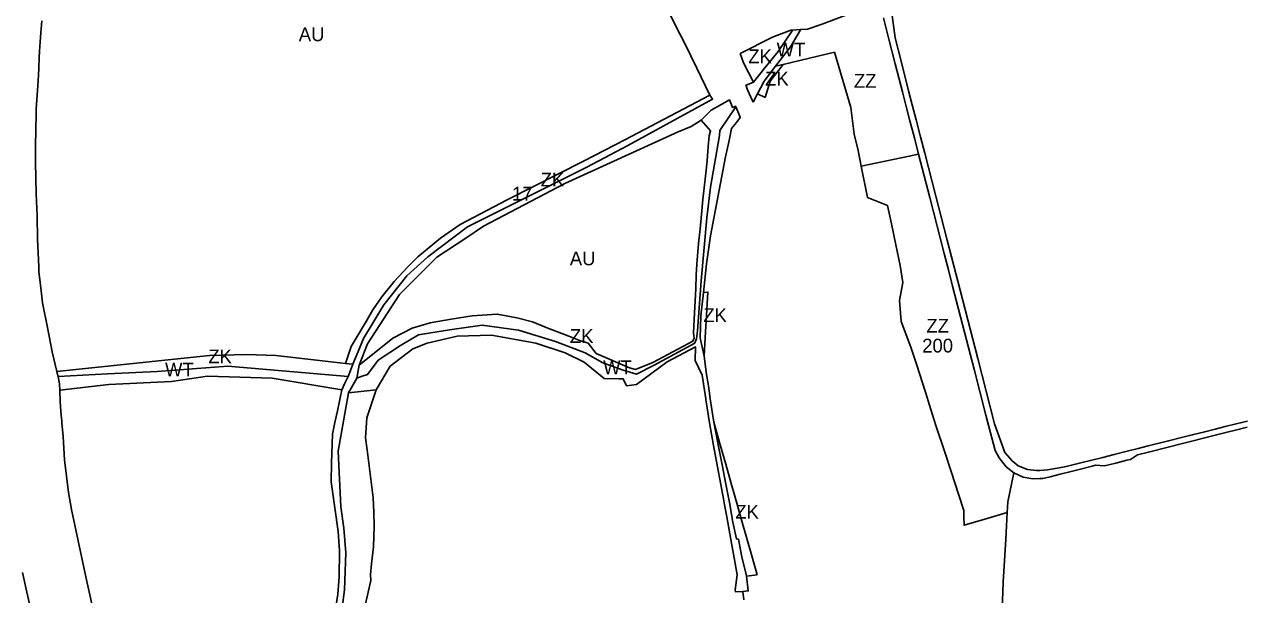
# Model space of a CAD drawing. Extents: x -521939 to -516426, y -1197857 to -1189551.
# Drawn here: x -520821 to -519936, y -1191056 to -1190643 of the extents above; entities that cross this region are included whole.
import ezdxf

# ---------------------------------------------------------------- set-up
doc = ezdxf.new("R2010")
doc.units = 0
for name, color, linetype in [('90640013', 7, 'Continuous'), ('90670013', 7, 'Continuous'), ('90670023', 7, 'Continuous'), ('90710013', 7, 'Continuous'), ('90710023', 7, 'Continuous'), ('90750013', 7, 'Continuous'), ('90760013', 7, 'Continuous'), ('ID_navrh', 7, 'Continuous')]:
    doc.layers.add(name, color=color, linetype=linetype)

msp = doc.modelspace()

# ---------------------------------------------------------------- linework, layer by layer
at = {"layer": '90640013'}
for points in [[(-520293.09, -1190699.05), (-520289.87, -1190692.86), (-520285.12, -1190683.72), (-520277.02, -1190672.92), (-520266.06, -1190658.73), (-520258.89, -1190646.59), (-520258.89, -1190646.14), (-520264.87, -1190646.73), (-520264.75, -1190647.22), (-520275.05, -1190662.18), (-520284.6, -1190674.13), (-520292.81, -1190684.4), (-520297.57, -1190686.32), (-520298.45, -1190686.69), (-520298.24, -1190687.15), (-520297.09, -1190690.03), (-520294.84, -1190695.28), (-520293.32, -1190698.51), (-520293.09, -1190699.05)], [(-520300.69, -1191053.74), (-520296.62, -1191053.24), (-520297.9, -1191042.46), (-520298.38, -1191040.48), (-520301.26, -1191028.49), (-520303.81, -1191015.76), (-520305.26, -1191015.58), (-520307.87, -1191003.34), (-520308.58, -1190999.2), (-520310.09, -1190990.35), (-520312.91, -1190975.8), (-520315.64, -1190961.74), (-520315.85, -1190960.65), (-520318.42, -1190947.44), (-520318.74, -1190945.79), (-520321.62, -1190930.94), (-520323.01, -1190921.74), (-520324.17, -1190914.08), (-520324.81, -1190909.83), (-520325.83, -1190903.07), (-520326.85, -1190896.32), (-520328.57, -1190882.98), (-520331.4, -1190869.77), (-520330.94, -1190853.79), (-520329.11, -1190836.87), (-520326.88, -1190816.15), (-520324.02, -1190795.87), (-520313.16, -1190738.47), (-520310.59, -1190726.63), (-520308.72, -1190718.11), (-520305.27, -1190713.64), (-520302.42, -1190709.94), (-520303.5, -1190707.28), (-520305.63, -1190702.37), (-520317.2, -1190719.56), (-520317.55, -1190723.04), (-520324.05, -1190760.6), (-520326.6, -1190782.85), (-520330.8, -1190828.36), (-520333.48, -1190864.82), (-520334.12, -1190870.43), (-520335.3, -1190873.36), (-520335.39, -1190873.58), (-520364.84, -1190889.55), (-520377.6, -1190896.01), (-520387.42, -1190893.21), (-520401.95, -1190887.98), (-520414.96, -1190880.71), (-520436.37, -1190872.55), (-520463.15, -1190864.14), (-520489.53, -1190860.7), (-520513.25, -1190864.01), (-520535.56, -1190867.71), (-520548.81, -1190875.36), (-520564.88, -1190886.07), (-520572.53, -1190896.27), (-520576.48, -1190897.66), (-520580.44, -1190899.06), (-520586.27, -1190909.59), (-520566.41, -1190907.41), (-520556.17, -1190890.3), (-520539.78, -1190877.79), (-520529.48, -1190873.72), (-520507.51, -1190868.51), (-520482.81, -1190867.75), (-520450.71, -1190873.64), (-520429.39, -1190880.67), (-520415.69, -1190887.37), (-520401.05, -1190899.23), (-520390.41, -1190899.46), (-520387.21, -1190899.53), (-520384.79, -1190904.6), (-520377.57, -1190903.54), (-520355.52, -1190887.16), (-520334.81, -1190876.42), (-520335.23, -1190886.32), (-520330.14, -1190896.79), (-520327.45, -1190914.09), (-520327.38, -1190914.52), (-520324.76, -1190931.38), (-520324.76, -1190931.39), (-520321.74, -1190947.87), (-520319.13, -1190962.12), (-520316.55, -1190976.2), (-520314.68, -1190986.43), (-520313.89, -1190990.74), (-520312.27, -1190999.57), (-520309.26, -1191016.03), (-520306.84, -1191029.26), (-520304.6, -1191041.48), (-520306.2, -1191052.37), (-520305.85, -1191054), (-520300.69, -1191053.74)], [(-520795.63, -1190907.7), (-520760.13, -1190903.61), (-520714.74, -1190901.46), (-520688.67, -1190897.65), (-520641.66, -1190899.02), (-520591.21, -1190907.38), (-520588.94, -1190902.65), (-520586.68, -1190897.92), (-520673.92, -1190890.22), (-520725.06, -1190894.18), (-520760.94, -1190895.97), (-520796.83, -1190897.77), (-520795.84, -1190903.04), (-520795.63, -1190907.7)]]:
    msp.add_lwpolyline(points, dxfattribs=at)
at = {"layer": '90670013'}
for points in [[(-520212.3, -1190630.74), (-520243.84, -1190642.67), (-520253.81, -1190645.91), (-520258.89, -1190646.14), (-520258.89, -1190646.59), (-520266.06, -1190658.73), (-520277.02, -1190672.92)], [(-520277.02, -1190672.92), (-520271.45, -1190671.59), (-520234.25, -1190662.74), (-520223.64, -1190698.57), (-520222.41, -1190702.71), (-520221.14, -1190712.4), (-520219.87, -1190722.1), (-520217, -1190733.95), (-520214.93, -1190745.28), (-520179.93, -1190738.09), (-520173.21, -1190736.7), (-520176.29, -1190724.77), (-520179.47, -1190712.51), (-520182.14, -1190702.16), (-520184.89, -1190691.51), (-520190.1, -1190671.19), (-520194.85, -1190653.37), (-520198.74, -1190637.77)], [(-519935.17, -1190934.6), (-519942.63, -1190936.51), (-519950.59, -1190938.53), (-519958.33, -1190940.45), (-519965.72, -1190942.29), (-519975.1, -1190944.67), (-519983.03, -1190946.64), (-519992.34, -1190949.01), (-520006.62, -1190952.57), (-520014.63, -1190954.57), (-520019.58, -1190957.88), (-520022.33, -1190958.55), (-520030.34, -1190960.58), (-520038.54, -1190962.66), (-520045.1, -1190962.2), (-520047.4, -1190962.76), (-520055.99, -1190964.97), (-520062.63, -1190966.61), (-520070.6, -1190968.71), (-520077.83, -1190970.45), (-520083.18, -1190971.78), (-520085.31, -1190971.83), (-520090.37, -1190971.94), (-520097.48, -1190970.69), (-520104.07, -1190967.71), (-520108.58, -1190988.66), (-520109.01, -1190996.4)], [(-520109.01, -1190996.4), (-520110.09, -1191015.65), (-520111.98, -1191046.9), (-520113.12, -1191080.75)]]:
    msp.add_lwpolyline(points, dxfattribs=at)
at = {"layer": '90670023'}
msp.add_lwpolyline([(-520109.01, -1190996.4), (-520108.58, -1190988.66), (-520104.07, -1190967.71), (-520109.65, -1190963.19), (-520114.88, -1190956.87), (-520117.77, -1190951.37), (-520124.37, -1190925.82), (-520132.72, -1190893.53), (-520148.53, -1190832.37), (-520151.61, -1190820.43), (-520154.72, -1190808.75), (-520165.15, -1190767.99), (-520173.21, -1190736.7), (-520179.93, -1190738.09), (-520214.93, -1190745.28), (-520210.17, -1190768.14), (-520195.82, -1190773.79), (-520192.9, -1190787.25), (-520189.71, -1190802.47), (-520186.5, -1190817.43), (-520184.56, -1190829.71), (-520187.09, -1190842.73), (-520185.78, -1190857.9), (-520178.77, -1190876.6), (-520174.75, -1190888.89), (-520170.2, -1190903.06), (-520166.97, -1190913.13), (-520165.54, -1190917.99), (-520160.67, -1190933.26), (-520154.54, -1190951.95), (-520149.48, -1190967.38), (-520144.26, -1190983.08), (-520140.38, -1190994.99), (-520140.34, -1190999.22), (-520140.24, -1191005.63), (-520125.17, -1191001.18), (-520109.01, -1190996.4)], dxfattribs=at)
at = {"layer": '90710013'}
for points in [[(-520302.58, -1190663.54), (-520300.02, -1190670.48), (-520292.81, -1190684.4), (-520284.6, -1190674.13), (-520275.05, -1190662.18), (-520264.75, -1190647.22), (-520264.87, -1190646.73), (-520265.85, -1190646.71), (-520279.12, -1190651.75), (-520302.58, -1190663.54)], [(-520277.02, -1190672.92), (-520285.12, -1190683.72), (-520289.87, -1190692.86), (-520284.45, -1190695.5), (-520280.67, -1190683.81), (-520271.45, -1190671.59), (-520277.02, -1190672.92)], [(-520305.63, -1190702.37), (-520305.81, -1190701.95), (-520308.05, -1190702.75), (-520308.79, -1190700.97), (-520310.32, -1190697.3), (-520315.88, -1190700.41), (-520323.58, -1190704.71), (-520330.69, -1190711.95), (-520323.95, -1190719.72), (-520325.05, -1190723.41), (-520325.74, -1190730.96), (-520326.54, -1190741.48), (-520327.34, -1190750.35), (-520328.73, -1190760.96), (-520329.54, -1190769.54), (-520330.54, -1190780.41), (-520331.56, -1190790.73), (-520332.67, -1190801.31), (-520333.97, -1190816.37), (-520334.36, -1190824.3), (-520334.74, -1190833.97), (-520335.62, -1190851.82), (-520336.05, -1190861.25), (-520336.25, -1190866.24), (-520335.85, -1190869.91), (-520336.87, -1190872.22), (-520365.72, -1190887.7), (-520378.38, -1190892.69), (-520382.74, -1190891.46), (-520406.81, -1190881.06), (-520412.64, -1190873.72), (-520419.4, -1190871.46), (-520426.72, -1190868.51), (-520434.99, -1190865.31), (-520443.11, -1190862.23), (-520452.97, -1190858.3), (-520464.28, -1190855.19), (-520472.23, -1190853.76), (-520478.57, -1190852.6), (-520496.68, -1190853.87), (-520511.96, -1190856.2), (-520527.22, -1190858.82), (-520540.12, -1190862.8), (-520554.25, -1190870.14), (-520578.54, -1190889.51), (-520580.44, -1190899.06), (-520576.48, -1190897.66), (-520572.53, -1190896.27), (-520564.88, -1190886.07), (-520548.81, -1190875.36), (-520535.56, -1190867.71), (-520513.25, -1190864.01), (-520489.53, -1190860.7), (-520463.15, -1190864.14), (-520436.37, -1190872.55), (-520414.96, -1190880.71), (-520401.95, -1190887.98), (-520387.42, -1190893.21), (-520377.6, -1190896.01), (-520364.84, -1190889.55), (-520335.39, -1190873.58), (-520335.3, -1190873.36), (-520334.12, -1190870.43), (-520333.48, -1190864.82), (-520330.8, -1190828.36), (-520326.6, -1190782.85), (-520324.05, -1190760.6), (-520317.55, -1190723.04), (-520317.2, -1190719.56), (-520305.63, -1190702.37)], [(-520329.11, -1190836.87), (-520330.94, -1190853.79), (-520331.4, -1190869.77), (-520328.57, -1190882.98), (-520327.81, -1190869.44), (-520326.9, -1190853.42), (-520325.95, -1190836.56), (-520329.11, -1190836.87)], [(-520588.66, -1190888.36), (-520639.13, -1190882.59), (-520660.25, -1190881.76), (-520687.09, -1190882.55), (-520797.73, -1190894.1), (-520797.4, -1190895.45), (-520796.83, -1190897.77), (-520760.94, -1190895.97), (-520725.06, -1190894.18), (-520673.92, -1190890.22), (-520586.68, -1190897.92), (-520584.97, -1190893.45), (-520583.27, -1190888.97), (-520588.66, -1190888.36)], [(-520577.05, -1191075.31), (-520570.23, -1191045.78), (-520570.41, -1191041.39), (-520569.74, -1191033.64), (-520568.24, -1191021.29), (-520567.88, -1191006.32), (-520568.13, -1190996.21), (-520568.6, -1190985.69), (-520570, -1190974.1), (-520572.82, -1190951.02), (-520573.95, -1190942.37), (-520573.11, -1190927.85), (-520566.41, -1190907.41), (-520586.27, -1190909.59), (-520593.76, -1190951.86), (-520592.04, -1190992.31), (-520589.79, -1191007.77), (-520588.39, -1191025.58), (-520589.24, -1191052.36), (-520591.05, -1191065.64)], [(-520290.15, -1191041.66), (-520294.1, -1191027.75), (-520297.68, -1191015.17), (-520301.24, -1191002.65), (-520304.9, -1190989.75), (-520305.89, -1190986.3), (-520308.99, -1190975.37), (-520312.95, -1190961.45), (-520316.98, -1190947.25), (-520321.62, -1190930.94), (-520318.74, -1190945.79), (-520318.42, -1190947.44), (-520315.85, -1190960.65), (-520315.64, -1190961.74), (-520312.91, -1190975.8), (-520310.09, -1190990.35), (-520308.58, -1190999.2), (-520307.87, -1191003.34), (-520305.26, -1191015.58), (-520303.81, -1191015.76), (-520301.26, -1191028.49), (-520298.38, -1191040.48), (-520297.9, -1191042.46), (-520290.15, -1191041.66)]]:
    msp.add_lwpolyline(points, dxfattribs=at)
at = {"layer": '90710023'}
msp.add_lwpolyline([(-520588.66, -1190888.36), (-520583.27, -1190888.97), (-520579.33, -1190879.67), (-520575.39, -1190870.36), (-520560.86, -1190845.88), (-520544.03, -1190824.72), (-520528.99, -1190810.95), (-520500.11, -1190789.41), (-520469.27, -1190773.73), (-520413.62, -1190746.07), (-520383.85, -1190730.39), (-520322.54, -1190696.8), (-520323.5, -1190695.35), (-520324.46, -1190693.89), (-520386.14, -1190726.13), (-520415.61, -1190741.57), (-520471.38, -1190769.62), (-520505.39, -1190787.53), (-520519.61, -1190797.43), (-520536.03, -1190811), (-520543.12, -1190818.16), (-520553.22, -1190828.97), (-520562.17, -1190840.06), (-520568.69, -1190849.57), (-520573.57, -1190857.84), (-520584.48, -1190876.05), (-520588.66, -1190888.36)], dxfattribs=at)
at = {"layer": '90750013'}
for points in [[(-520588.66, -1190888.36), (-520584.48, -1190876.05), (-520573.57, -1190857.84), (-520568.69, -1190849.57), (-520562.17, -1190840.06), (-520553.22, -1190828.97), (-520543.12, -1190818.16), (-520536.03, -1190811), (-520519.61, -1190797.43), (-520505.39, -1190787.53), (-520471.38, -1190769.62), (-520415.61, -1190741.57), (-520386.14, -1190726.13), (-520324.46, -1190693.89), (-520334, -1190674.28), (-520342.71, -1190656.38), (-520345.65, -1190650.45), (-520358.66, -1190624.95)], [(-520192.44, -1190636.14), (-520190.15, -1190652.41), (-520185.7, -1190670.28), (-520180.5, -1190690.67), (-520177.82, -1190700.89), (-520175.07, -1190711.67), (-520171.9, -1190723.98), (-520168.76, -1190735.95), (-520160.7, -1190767.16), (-520152.5, -1190799.08), (-520143.17, -1190835.12), (-520130.36, -1190884.81), (-520118.11, -1190932.22), (-520110.62, -1190952.85), (-520105.42, -1190959.01), (-520101.06, -1190962.64), (-520094.18, -1190965.2), (-520087.88, -1190966), (-520085.19, -1190966.03), (-520079.75, -1190965.36), (-520069.92, -1190963.7), (-520066.19, -1190963.08), (-520062.47, -1190962.13), (-520055.65, -1190960.44), (-520047.59, -1190958.43), (-520039.61, -1190956.43), (-520031.59, -1190954.41), (-520022.16, -1190952.02), (-520014.15, -1190950.02), (-520006.72, -1190948.17), (-519991.99, -1190944.47), (-519982.65, -1190942.1), (-519974.87, -1190940.16), (-519965.83, -1190937.89), (-519958.21, -1190935.99), (-519951.02, -1190934.14), (-519943.05, -1190932.07), (-519934.89, -1190930.13)], [(-520808.7, -1190640.05), (-520809.38, -1190648.62), (-520809.76, -1190655.1), (-520810.21, -1190661.95), (-520810.49, -1190666.44), (-520810.86, -1190674.27), (-520811.13, -1190679.39), (-520811.58, -1190686.99), (-520812.74, -1190703.8), (-520812.83, -1190707.72), (-520813.31, -1190730.65), (-520813.33, -1190742.53), (-520812.68, -1190765.38), (-520812.06, -1190781.24), (-520811.77, -1190798.26), (-520810.92, -1190818.26), (-520810.72, -1190821.89), (-520810.29, -1190825.6), (-520809.15, -1190835.67), (-520808.06, -1190844.37), (-520804.62, -1190862.21), (-520801.14, -1190879.93), (-520797.73, -1190894.1), (-520687.09, -1190882.55), (-520660.25, -1190881.76), (-520639.13, -1190882.59), (-520588.66, -1190888.36)], [(-520578.54, -1190889.51), (-520554.25, -1190870.14), (-520540.12, -1190862.8), (-520527.22, -1190858.82), (-520511.96, -1190856.2), (-520496.68, -1190853.87), (-520478.57, -1190852.6), (-520472.23, -1190853.76), (-520464.28, -1190855.19), (-520452.97, -1190858.3), (-520443.11, -1190862.23), (-520434.99, -1190865.31), (-520426.72, -1190868.51), (-520419.4, -1190871.46), (-520412.64, -1190873.72), (-520406.81, -1190881.06), (-520382.74, -1190891.46), (-520378.38, -1190892.69), (-520365.72, -1190887.7), (-520336.87, -1190872.22), (-520335.85, -1190869.91), (-520336.25, -1190866.24), (-520336.05, -1190861.25), (-520335.62, -1190851.82), (-520334.74, -1190833.97), (-520334.36, -1190824.3), (-520333.97, -1190816.37), (-520332.67, -1190801.31), (-520331.56, -1190790.73), (-520330.54, -1190780.41), (-520329.54, -1190769.54), (-520328.73, -1190760.96), (-520327.34, -1190750.35), (-520326.54, -1190741.48), (-520325.74, -1190730.96), (-520325.05, -1190723.41), (-520323.95, -1190719.72), (-520330.69, -1190711.95), (-520337.94, -1190716.53), (-520347.53, -1190720.51), (-520429.7, -1190757.81), (-520488.55, -1190788.82), (-520501.34, -1190797.6), (-520522.25, -1190811.26), (-520530.27, -1190819.39), (-520549.3, -1190838.28), (-520572.63, -1190874.12), (-520578.54, -1190889.51)]]:
    msp.add_lwpolyline(points, dxfattribs=at)
at = {"layer": '90760013'}
for points in [[(-520300.69, -1191053.74), (-520305.85, -1191054), (-520306.2, -1191052.37), (-520304.6, -1191041.48), (-520306.84, -1191029.26), (-520309.26, -1191016.03), (-520312.27, -1190999.57), (-520313.89, -1190990.74), (-520314.68, -1190986.43), (-520316.55, -1190976.2), (-520319.13, -1190962.12), (-520321.74, -1190947.87), (-520324.76, -1190931.39), (-520324.76, -1190931.38), (-520327.38, -1190914.52), (-520327.45, -1190914.09), (-520330.14, -1190896.79), (-520335.23, -1190886.32), (-520334.81, -1190876.42), (-520355.52, -1190887.16), (-520377.57, -1190903.54), (-520384.79, -1190904.6), (-520387.21, -1190899.53), (-520390.41, -1190899.46), (-520401.05, -1190899.23), (-520415.69, -1190887.37), (-520429.39, -1190880.67), (-520450.71, -1190873.64), (-520482.81, -1190867.75), (-520507.51, -1190868.51), (-520529.48, -1190873.72), (-520539.78, -1190877.79), (-520556.17, -1190890.3), (-520566.41, -1190907.41), (-520573.11, -1190927.85), (-520573.95, -1190942.37), (-520572.82, -1190951.02), (-520570, -1190974.1), (-520568.6, -1190985.69), (-520568.13, -1190996.21), (-520567.88, -1191006.32), (-520568.24, -1191021.29), (-520569.74, -1191033.64), (-520570.41, -1191041.39), (-520570.23, -1191045.78), (-520577.05, -1191075.31)], [(-520597.48, -1191077.12), (-520594.04, -1191055.69), (-520593.17, -1191043.04), (-520592.99, -1191024.28), (-520593.81, -1191010.23), (-520598.93, -1190974.08), (-520598.61, -1190960.68), (-520597.97, -1190939.69), (-520596.29, -1190931.07), (-520594.41, -1190922.81), (-520592.68, -1190914.39), (-520591.21, -1190907.38), (-520641.66, -1190899.02), (-520688.67, -1190897.65), (-520714.74, -1190901.46), (-520760.13, -1190903.61), (-520795.63, -1190907.7), (-520795.25, -1190916.18), (-520794.58, -1190926.05), (-520794.23, -1190929.98), (-520794.11, -1190931.35), (-520793.22, -1190941.3), (-520792.16, -1190958.16), (-520789.33, -1190981.89), (-520787.08, -1190994.15), (-520776.73, -1191043.11), (-520769.65, -1191074.63)], [(-520704.46, -1191503.52), (-520712.23, -1191475.88), (-520721.14, -1191444.12), (-520729.17, -1191413.61), (-520732.39, -1191401.49), (-520740.08, -1191370.95), (-520745.31, -1191350.43), (-520747.53, -1191341.72), (-520752.93, -1191320.48), (-520762.01, -1191284.51), (-520774.39, -1191235.28), (-520786.96, -1191185.86), (-520797.61, -1191144.17), (-520805.2, -1191114.16), (-520812.23, -1191086.24), (-520820.01, -1191052.05), (-520822.58, -1191039.85)], [(-520299.9, -1191059.72), (-520300.69, -1191053.74)]]:
    msp.add_lwpolyline(points, dxfattribs=at)

# ---------------------------------------------------------------- texts
at = {"layer": '90640013'}
for rotation, p in [(360, (-520276.07, -1190665.78)), (0, (-520401.82, -1190896.21)), (0, (-520719.35, -1190897.77))]:
    msp.add_text('WT', height=10, rotation=rotation, dxfattribs=at).set_placement(p)
at = {"layer": '90670013'}
msp.add_text('ZZ', height=10, rotation=360, dxfattribs=at).set_placement((-520220.09, -1190688.48))
at = {"layer": '90670023'}
msp.add_text('ZZ', height=10, rotation=360, dxfattribs=at).set_placement((-520167.61, -1190866.02))
at = {"layer": '90710013'}
for rotation, p in [(360, (-520296.65, -1190670.66)), (360, (-520284.47, -1190686.89)), (360, (-520329.24, -1190858.36)), (0, (-520425.94, -1190873.49)), (360, (-520688, -1190888.26)), (0, (-520306.05, -1191000.89))]:
    msp.add_text('ZK', height=10, rotation=rotation, dxfattribs=at).set_placement(p)
at = {"layer": '90710023'}
msp.add_text('ZK', height=10, dxfattribs=at).set_placement((-520447.11, -1190760.05))
at = {"layer": '90750013'}
for rotation, p in [(0, (-520622.41, -1190654.73)), (360, (-520425.98, -1190817.2))]:
    msp.add_text('AU', height=10, rotation=rotation, dxfattribs=at).set_placement(p)
at = {"layer": 'ID_navrh'}
for s, rotation, p in [('17', 0, (-520467.88, -1190770.29)), ('200', 360, (-520170.57, -1190880.42))]:
    msp.add_text(s, height=10, rotation=rotation, dxfattribs=at).set_placement(p)

doc.saveas('drawing.dxf')
